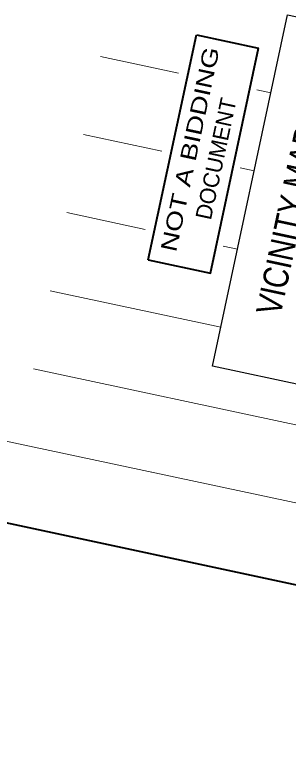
# Model space of a CAD drawing. Extents: x 2363411 to 2369126, y 6976878 to 6988319.
# Drawn here: x 2367640 to 2367982, y 6987389 to 6988319 of the extents above; entities that cross this region are included whole.
import ezdxf
from ezdxf.enums import TextEntityAlignment as Align

# ---------------------------------------------------------------- set-up
doc = ezdxf.new("R2010")
doc.units = 0
doc.header["$LTSCALE"] = 2
for name, color, linetype, lineweight in [('40', 7, 'Continuous', 13), ('44', 7, 'Continuous', 40), ('62', 7, 'Continuous', 13), ('63', 7, 'Continuous', 13)]:
    doc.layers.add(name, color=color, linetype=linetype, lineweight=lineweight)

msp = doc.modelspace()

# ---------------------------------------------------------------- linework, layer by layer
at = {"layer": '40'}
for p, q in [((2367747.348, 6988267.344), (2367845.145, 6988246.448)), ((2367942.942, 6988225.552), (2367960.662, 6988221.766)), ((2367726.452, 6988169.547), (2367824.249, 6988148.651)), ((2367922.046, 6988127.755), (2367939.766, 6988123.969)), ((2367705.556, 6988071.75), (2367803.353, 6988050.854)), ((2367901.149, 6988029.957), (2367918.87, 6988026.171)), ((2367684.66, 6987973.954), (2367897.975, 6987928.375)), ((2367663.763, 6987876.155), (2368449.239, 6987708.324))]:
    msp.add_line(p, q, dxfattribs=at)
at = {"layer": '44', "lineweight": 13}
msp.add_line((2365605.51, 6988218.434), (2369126.202, 6987466.173), dxfattribs=at)
at = {"layer": '44'}
msp.add_line((2365682.411, 6988099.741), (2369007.509, 6987389.272), dxfattribs=at)
at = {"layer": '62', "lineweight": 40}
for p, q in [((2367807.332, 6988012.569), (2367867.505, 6988294.188)), ((2367867.505, 6988294.188), (2367945.193, 6988277.589))]:
    msp.add_line(p, q, dxfattribs=at)
at = {"layer": '62', "lineweight": 25}
msp.add_lwpolyline([(2368004.774, 6987854.862), (2367887.617, 6987879.897), (2367981.487, 6988319.234), (2368098.715, 6988294.53)], dxfattribs=at)
at = {"layer": '62', "lineweight": 40}
msp.add_lwpolyline([(2367807.332, 6988012.569), (2367885.019, 6987995.97), (2367945.193, 6988277.589)], dxfattribs=at)
at = {"layer": '63', "lineweight": 40}
for p, q in [((2367807.332, 6988012.569), (2367867.505, 6988294.188)), ((2367867.505, 6988294.188), (2367945.193, 6988277.589))]:
    msp.add_line(p, q, dxfattribs=at)
at = {"layer": '63'}
for p, q in [((2367942.942, 6988225.552), (2367960.662, 6988221.766)), ((2367922.046, 6988127.755), (2367939.766, 6988123.969)), ((2367901.149, 6988029.957), (2367918.87, 6988026.171))]:
    msp.add_line(p, q, dxfattribs=at)
at = {"layer": '63', "lineweight": 25}
msp.add_lwpolyline([(2368004.774, 6987854.862), (2367887.617, 6987879.897), (2367981.487, 6988319.234), (2368098.715, 6988294.53)], dxfattribs=at)
at = {"layer": '63', "lineweight": 40}
msp.add_lwpolyline([(2367807.332, 6988012.569), (2367885.019, 6987995.97), (2367945.193, 6988277.589)], dxfattribs=at)

# ---------------------------------------------------------------- texts
at = {"layer": '62', "width": 1.3}
msp.add_text('NOT A BIDDING', height=20, rotation=77.939, dxfattribs=at).set_placement((2367869.286, 6988149.056), align=Align.CENTER)
at = {"layer": '62'}
msp.add_text('DOCUMENT', height=20, rotation=77.939, dxfattribs=at).set_placement((2367901.718, 6988137.158), align=Align.CENTER)
at = {"layer": '62', "width": 0.85}
msp.add_text('VICINITY MAP', height=31.45, rotation=77.939, dxfattribs=at).set_placement((2367972.632, 6987941.577))
at = {"layer": '63', "width": 1.3}
msp.add_text('NOT A BIDDING', height=20, rotation=77.939, dxfattribs=at).set_placement((2367869.286, 6988149.056), align=Align.CENTER)
at = {"layer": '63'}
msp.add_text('DOCUMENT', height=20, rotation=77.939, dxfattribs=at).set_placement((2367901.718, 6988137.158), align=Align.CENTER)
at = {"layer": '63', "width": 0.85}
msp.add_text('VICINITY MAP', height=31.45, rotation=77.939, dxfattribs=at).set_placement((2367972.632, 6987941.577))

doc.saveas('drawing.dxf')
